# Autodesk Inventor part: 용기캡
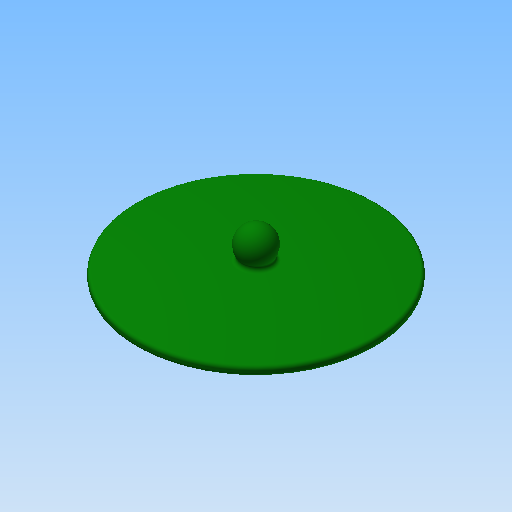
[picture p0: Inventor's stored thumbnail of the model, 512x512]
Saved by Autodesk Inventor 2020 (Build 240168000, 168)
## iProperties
Created: 2018-01
Part Number: 용기캡
Material: ABS 플라스틱
Document SubType Name: Modeling
Designer: mduedu
Density: 1 g/cm^3
Appearance: 진녹색
Author: mduedu
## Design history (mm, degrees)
sketch "스케치1"
  geometry: L1 (-35, 2.5)-(0, 2.5); L2 (0, 5)-(0, 0); L3 (0, 0)-(-35, 0); L4 (-35, 0)-(-35, 2.5); L5 (-31, 0)-(-29, 0); L6 (-29, 0)-(-29, -2); L7 (-29, -2)-(-31, -2); L8 (-31, -2)-(-31, 0); A1 r 246.25 centre (0, -241.25) between (0, 5) and (-35, 2.5); 1 further point
  constraints: 16 end point, 4 parallel, 2 horizontal, 2 perpendicular, 2 point on circle, 1 centre point, 1 coincident, 1 midpoint, 1 point on line, 1 vertical alignment
  dimensions: "d2" = 70 diameter of L4 L2; "d3" = 5 distance from line of L2.start L3; "d4" = 2.5 distance of L3.end L1.start; "d5" = 4 distance between parallel lines of L8 L4; "d6" = 2 distance of L6.end L7.end; "d7" = 2 distance between parallel lines of L7 L3
revolve "회전1" sketch "스케치1" stored, may be unused: angle "d8" = 90 deg
chamfer "모따기1" distance "d9" = 0.5; stored, may be unused: second distance "d10" = 2, angle "d11" = 45 deg
fillet "모깎기1" dims "d12" = 1
fillet "모깎기2" dims "d13" = 1
sketch "스케치2"
  geometry: L1 (-30.5, -2)-(-31, -1.5) reference; L2 (-31, -1.5)-(-31, 0) reference; L3 (-31, 0)-(-34, 0) reference; L4 (-35, 1)-(-35, 1.632) reference; L5 (35, 1.632)-(35, 1) reference; L6 (34, 0)-(31, 0) reference; L7 (31, 0)-(31, -1.5) reference; L8 (31, -1.5)-(30.5, -2) reference; L9 (30.5, -2)-(29, -2) reference; L10 (29, -2)-(29, -1) reference; L11 (28, 0)-(-28, 0) reference; L12 (-29, -1)-(-29, -2) reference; L13 (-29, -2)-(-30.5, -2) reference; L14 (0, 14)-(0, 4); A1 r 1 centre (-34, 1) between (-35, 1) and (-34, 0) reference; A2 r 1 centre (-34, 1.632) between (-34.139, 2.622) and (-35, 1.632) reference; A3 r 246.25 centre (0, -241.25) between (34.139, 2.622) and (-34.139, 2.622) reference; A4 r 1 centre (34, 1.632) between (35, 1.632) and (34.139, 2.622) reference; A5 r 1 centre (34, 1) between (34, 0) and (35, 1) reference; A6 r 1 centre (28, -1) between (29, -1) and (28, 0) reference; A7 r 1 centre (-28, -1) between (-28, 0) and (-29, -1) reference; A8 r 5 centre (0, 9) between (0, 14) and (0, 4); 3 further points
  constraints: 2 end point, 2 midpoint, 2 point on circle, 1 centre point, 1 coincident, 1 perpendicular, 1 point on line, 1 vertical alignment
  dimensions: "d14" = 10 diameter of A8; "d16" = 9 distance of A8.centre point (0, 0)
revolve "회전2" sketch "스케치2" stored, may be unused: angle "d17" = 90 deg
fillet "모깎기3" dims "d18" = 1
node "솔리드1"
node "절단 모서리 투영1"
